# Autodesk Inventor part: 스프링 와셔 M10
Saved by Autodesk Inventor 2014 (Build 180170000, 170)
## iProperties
Created: 2026-06
Part Number: 스프링 와셔 M10
Material: 강철, 연강
Document SubType Name: Modeling
Designer: dg
Density: 7.86 g/cm^3
Appearance: 강철
Mass: 3.10189 g
Surface Area: 5.48825 cm^2
Volume: 0.394643 cm^3
Author: jhkim
Description: 스프링 잠금 와셔
Creation Date: 2026-05-29
Sending System: Autodesk Inventor 2027
Preprocessor: ST-DEVELOPER v20.1
Author: dg
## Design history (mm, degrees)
node "스프링 와셔 M101"
body "Solid1"
node "기준1"
